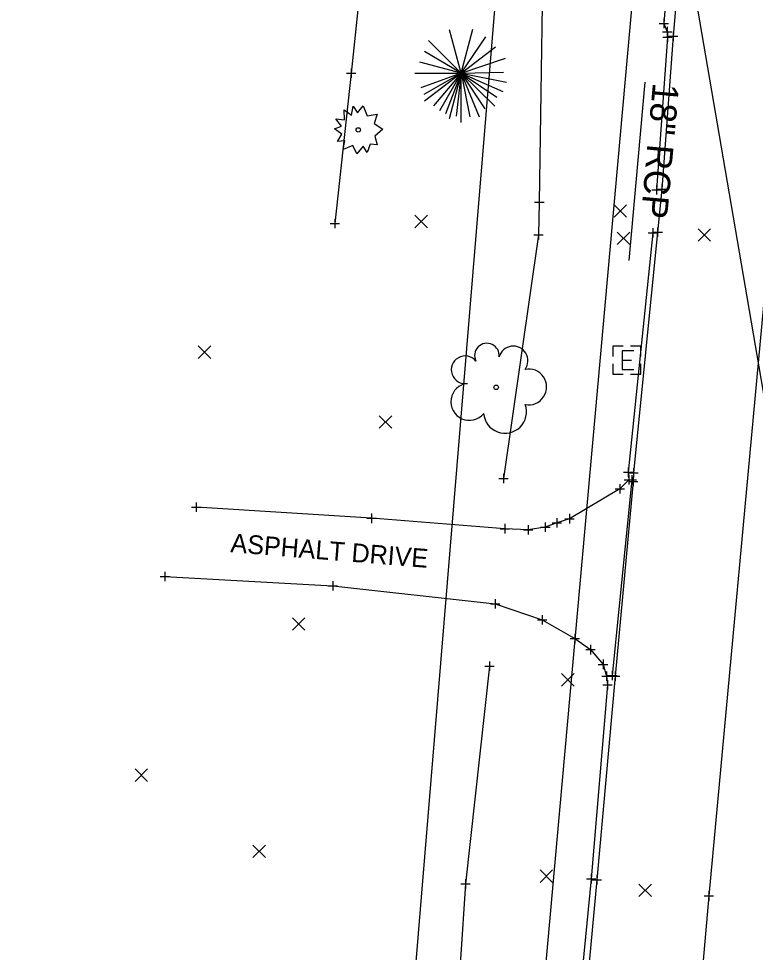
# Model space of a CAD drawing. Extents: x 1380550 to 1381945, y 468927 to 470496.
# Drawn here: x 1381450.4 to 1381528.9, y 469059.1 to 469158.5 of the extents above; entities that cross this region are included whole.
import ezdxf

# ---------------------------------------------------------------- set-up
doc = ezdxf.new("R2010")
doc.units = 0
for name, color, linetype in [('DR_X_Storm_Sewer', 7, 'Continuous'), ('DR_X_Text', 7, 'Continuous'), ('PV_X_COP', 7, 'Continuous'), ('PV_X_Curb', 7, 'Continuous'), ('PV_X_Driveway', 7, 'Continuous'), ('PV_X_EOP', 7, 'Continuous'), ('RD_X_Text', 7, 'Continuous'), ('RW_X_Esmt_General', 7, 'Continuous'), ('SV_X_Random_Point', 7, 'Continuous'), ('SV_X_Shot_Marker', 7, 'Continuous'), ('SV_X_Toe_of_Slope', 7, 'Continuous'), ('UT_X_Electric', 7, 'Continuous'), ('UT_X_Electric_Cells', 7, 'Continuous'), ('UT_X_Telecom', 7, 'Continuous'), ('VG_X_Cells', 7, 'Continuous')]:
    doc.layers.add(name, color=color, linetype=linetype)

msp = doc.modelspace()

# ---------------------------------------------------------------- linework, layer by layer
at = {"layer": 'DR_X_Storm_Sewer'}
msp.add_line((1381528.037, 469296.447), (1381500.707, 468992.415), dxfattribs=at)
at = {"layer": 'DR_X_Text'}
msp.add_line((1381515.48, 469132.742), (1381517.189, 469151.751), dxfattribs=at)
at = {"layer": 'PV_X_COP'}
msp.add_lwpolyline([(1381585.986, 469815.579), (1381581.288, 469760.779), (1381580.3, 469747.86), (1381578.724, 469729.445), (1381576.782, 469708.953), (1381575.288, 469689.792), (1381572.756, 469657.561), (1381569.364, 469615.703), (1381565.36, 469567.235), (1381561.161, 469537.516), (1381558.939, 469486.814), (1381555.385, 469442.034), (1381550.974, 469391.016), (1381547.282, 469345.901), (1381541.953, 469289.547), (1381537.187, 469231.269), (1381533.052, 469168.087), (1381530.317, 469133.741), (1381523.968, 469065.081), (1381520.119, 469021.37), (1381518.183, 469001.306)], dxfattribs=at)
at = {"layer": 'PV_X_Curb'}
for points in [[(1381519.539, 469157.132), (1381519.552, 469156.548), (1381518.398, 469140.282)], [(1381518.001, 469135.707), (1381515.357, 469110.199), (1381515.44, 469109.406)], [(1381513.052, 469088.479), (1381513.166, 469087.561), (1381511.423, 469066.882), (1381509.25, 469044.753), (1381508.961, 469043.741)]]:
    msp.add_lwpolyline(points, dxfattribs=at)
at = {"layer": 'PV_X_Driveway'}
for points in [[(1381487.828, 469171.671), (1381488.593, 469175.573), (1381489.804, 469177.06), (1381491.802, 469178.459), (1381493.744, 469178.705), (1381499.999, 469178.744), (1381505.248, 469177.971), (1381510.629, 469175.939), (1381513.747, 469175.079), (1381519.994, 469168.458), (1381519.164, 469158.007), (1381519.539, 469157.132)], [(1381487.828, 469171.671), (1381485.847, 469152.719), (1381484.107, 469136.687)], [(1381515.44, 469109.406), (1381514.47, 469108.44), (1381509.128, 469105.258), (1381507.755, 469104.815), (1381506.539, 469104.347), (1381504.719, 469104.064), (1381502.211, 469104.195), (1381488.025, 469105.298), (1381469.315, 469106.486)], [(1381515.44, 469109.406), (1381515.744, 469109.385), (1381513.68, 469088.547), (1381513.052, 469088.479)], [(1381465.962, 469099.103), (1381483.882, 469098.094), (1381501.198, 469096.181), (1381506.201, 469094.476), (1381509.674, 469092.506), (1381511.352, 469091.307), (1381512.688, 469089.742), (1381513.052, 469088.479)]]:
    msp.add_lwpolyline(points, dxfattribs=at)
at = {"layer": 'PV_X_EOP'}
msp.add_lwpolyline([(1381521.185, 469168.775), (1381520.163, 469156.66), (1381518.942, 469140.358), (1381518.512, 469135.769), (1381515.95, 469110.139), (1381515.909, 469109.22), (1381513.991, 469088.497), (1381512.042, 469066.797), (1381509.955, 469044.61), (1381509.763, 469043.721), (1381507.936, 469023.869), (1381507.813, 469022.448), (1381506.018, 469002.556)], dxfattribs=at)
at = {"layer": 'RW_X_Esmt_General'}
msp.add_lwpolyline([(1381490.401, 469029.464), (1381590.199, 470237.184), (1380558.689, 470277.035)], dxfattribs=at)
at = {"layer": 'SV_X_Random_Point'}
for p, q in [((1381513.872, 469137.363), (1381515.206, 469138.698)), ((1381513.872, 469138.698), (1381515.206, 469137.363)), ((1381492.645, 469136.244), (1381493.979, 469137.579)), ((1381492.645, 469137.579), (1381493.979, 469136.244)), ((1381522.821, 469134.808), (1381524.155, 469136.143)), ((1381522.821, 469136.143), (1381524.155, 469134.808)), ((1381514.203, 469134.449), (1381515.537, 469135.784)), ((1381514.203, 469135.784), (1381515.537, 469134.449)), ((1381469.53, 469122.328), (1381470.864, 469123.663)), ((1381469.53, 469123.663), (1381470.864, 469122.328)), ((1381488.825, 469114.889), (1381490.159, 469116.224)), ((1381488.825, 469116.224), (1381490.159, 469114.889)), ((1381479.569, 469093.38), (1381480.903, 469094.715)), ((1381479.569, 469094.715), (1381480.903, 469093.38)), ((1381508.277, 469087.419), (1381509.611, 469088.754)), ((1381508.277, 469088.754), (1381509.611, 469087.419)), ((1381462.799, 469077.27), (1381464.133, 469078.606)), ((1381462.799, 469078.606), (1381464.133, 469077.27)), ((1381475.372, 469069.164), (1381476.706, 469070.499)), ((1381475.372, 469070.499), (1381476.706, 469069.164)), ((1381505.984, 469066.516), (1381507.318, 469067.851)), ((1381505.984, 469067.851), (1381507.318, 469066.516)), ((1381516.522, 469065.008), (1381517.856, 469066.343)), ((1381516.522, 469066.343), (1381517.856, 469065.008))]:
    msp.add_line(p, q, dxfattribs=at)
at = {"layer": 'SV_X_Shot_Marker'}
for p, q in [((1381518.664, 469158.007), (1381519.664, 469158.007)), ((1381519.164, 469158.507), (1381519.164, 469157.507)), ((1381519.164, 469158.007), (1381519.164, 469158.007)), ((1381519.039, 469157.132), (1381520.039, 469157.132)), ((1381519.039, 469157.132), (1381520.039, 469157.132)), ((1381519.539, 469157.632), (1381519.539, 469156.632)), ((1381519.539, 469157.632), (1381519.539, 469156.632)), ((1381519.539, 469157.132), (1381519.539, 469157.132)), ((1381519.539, 469157.132), (1381519.539, 469157.132)), ((1381519.552, 469157.048), (1381519.552, 469156.048)), ((1381520.163, 469157.16), (1381520.163, 469156.16)), ((1381519.052, 469156.548), (1381520.052, 469156.548)), ((1381519.552, 469156.548), (1381519.552, 469156.548)), ((1381519.663, 469156.66), (1381520.663, 469156.66)), ((1381520.163, 469156.66), (1381520.163, 469156.66)), ((1381485.847, 469153.219), (1381485.847, 469152.219)), ((1381485.347, 469152.719), (1381486.347, 469152.719)), ((1381485.847, 469152.719), (1381485.847, 469152.719)), ((1381517.898, 469140.282), (1381518.898, 469140.282)), ((1381518.398, 469140.782), (1381518.398, 469139.782)), ((1381518.398, 469140.282), (1381518.398, 469140.282)), ((1381518.442, 469140.358), (1381519.442, 469140.358)), ((1381518.942, 469140.858), (1381518.942, 469139.858)), ((1381518.942, 469140.358), (1381518.942, 469140.358)), ((1381505.898, 469139.484), (1381505.898, 469138.484)), ((1381505.398, 469138.984), (1381506.398, 469138.984)), ((1381505.898, 469138.984), (1381505.898, 469138.984)), ((1381484.107, 469137.187), (1381484.107, 469136.187)), ((1381483.607, 469136.687), (1381484.607, 469136.687)), ((1381484.107, 469136.687), (1381484.107, 469136.687)), ((1381518.001, 469136.207), (1381518.001, 469135.207)), ((1381518.512, 469136.269), (1381518.512, 469135.269)), ((1381505.326, 469135.51), (1381506.326, 469135.51)), ((1381505.826, 469136.01), (1381505.826, 469135.01)), ((1381505.826, 469135.51), (1381505.826, 469135.51)), ((1381517.501, 469135.707), (1381518.501, 469135.707)), ((1381518.001, 469135.707), (1381518.001, 469135.707)), ((1381518.012, 469135.769), (1381519.012, 469135.769)), ((1381518.512, 469135.769), (1381518.512, 469135.769)), ((1381514.857, 469110.199), (1381515.857, 469110.199)), ((1381515.357, 469110.699), (1381515.357, 469109.699)), ((1381515.357, 469110.199), (1381515.357, 469110.199)), ((1381515.95, 469110.639), (1381515.95, 469109.639)), ((1381501.565, 469109.541), (1381502.565, 469109.541)), ((1381502.065, 469110.041), (1381502.065, 469109.041)), ((1381502.065, 469109.541), (1381502.065, 469109.541)), ((1381514.94, 469109.406), (1381515.94, 469109.406)), ((1381514.94, 469109.406), (1381515.94, 469109.406)), ((1381514.94, 469109.406), (1381515.94, 469109.406)), ((1381515.244, 469109.385), (1381516.244, 469109.385)), ((1381515.409, 469109.22), (1381516.409, 469109.22)), ((1381515.44, 469109.906), (1381515.44, 469108.906)), ((1381515.44, 469109.906), (1381515.44, 469108.906)), ((1381515.44, 469109.906), (1381515.44, 469108.906)), ((1381515.44, 469109.406), (1381515.44, 469109.406)), ((1381515.44, 469109.406), (1381515.44, 469109.406)), ((1381515.44, 469109.406), (1381515.44, 469109.406)), ((1381515.45, 469110.139), (1381516.45, 469110.139)), ((1381515.744, 469109.885), (1381515.744, 469108.885)), ((1381515.744, 469109.385), (1381515.744, 469109.385)), ((1381515.909, 469109.72), (1381515.909, 469108.72)), ((1381515.909, 469109.22), (1381515.909, 469109.22)), ((1381515.95, 469110.139), (1381515.95, 469110.139)), ((1381513.97, 469108.44), (1381514.97, 469108.44)), ((1381514.47, 469108.94), (1381514.47, 469107.94)), ((1381514.47, 469108.44), (1381514.47, 469108.44)), ((1381468.815, 469106.486), (1381469.815, 469106.486)), ((1381469.315, 469106.986), (1381469.315, 469105.986)), ((1381469.315, 469106.486), (1381469.315, 469106.486)), ((1381487.525, 469105.298), (1381488.525, 469105.298)), ((1381488.025, 469105.798), (1381488.025, 469104.798)), ((1381488.025, 469105.298), (1381488.025, 469105.298)), ((1381507.755, 469105.315), (1381507.755, 469104.315)), ((1381508.628, 469105.258), (1381509.628, 469105.258)), ((1381509.128, 469105.758), (1381509.128, 469104.758)), ((1381509.128, 469105.258), (1381509.128, 469105.258)), ((1381502.211, 469104.695), (1381502.211, 469103.695)), ((1381504.719, 469104.564), (1381504.719, 469103.564)), ((1381506.039, 469104.347), (1381507.039, 469104.347)), ((1381506.539, 469104.847), (1381506.539, 469103.847)), ((1381506.539, 469104.347), (1381506.539, 469104.347)), ((1381507.255, 469104.815), (1381508.255, 469104.815)), ((1381507.755, 469104.815), (1381507.755, 469104.815)), ((1381501.711, 469104.195), (1381502.711, 469104.195)), ((1381502.211, 469104.195), (1381502.211, 469104.195)), ((1381504.219, 469104.064), (1381505.219, 469104.064)), ((1381504.719, 469104.064), (1381504.719, 469104.064)), ((1381465.962, 469099.603), (1381465.962, 469098.603)), ((1381465.462, 469099.103), (1381466.462, 469099.103)), ((1381465.962, 469099.103), (1381465.962, 469099.103)), ((1381483.882, 469098.594), (1381483.882, 469097.594)), ((1381483.382, 469098.094), (1381484.382, 469098.094)), ((1381483.882, 469098.094), (1381483.882, 469098.094)), ((1381501.198, 469096.681), (1381501.198, 469095.681)), ((1381500.698, 469096.181), (1381501.698, 469096.181)), ((1381501.198, 469096.181), (1381501.198, 469096.181)), ((1381505.701, 469094.476), (1381506.701, 469094.476)), ((1381506.201, 469094.976), (1381506.201, 469093.976)), ((1381506.201, 469094.476), (1381506.201, 469094.476)), ((1381509.174, 469092.506), (1381510.174, 469092.506)), ((1381509.674, 469093.006), (1381509.674, 469092.006)), ((1381509.674, 469092.506), (1381509.674, 469092.506)), ((1381510.852, 469091.307), (1381511.852, 469091.307)), ((1381511.352, 469091.807), (1381511.352, 469090.807)), ((1381511.352, 469091.307), (1381511.352, 469091.307)), ((1381500.093, 469089.559), (1381501.093, 469089.559)), ((1381500.593, 469090.059), (1381500.593, 469089.059)), ((1381500.593, 469089.559), (1381500.593, 469089.559)), ((1381512.188, 469089.742), (1381513.188, 469089.742)), ((1381512.688, 469090.242), (1381512.688, 469089.242)), ((1381512.688, 469089.742), (1381512.688, 469089.742)), ((1381512.552, 469088.479), (1381513.552, 469088.479)), ((1381512.552, 469088.479), (1381513.552, 469088.479)), ((1381512.552, 469088.479), (1381513.552, 469088.479)), ((1381513.052, 469088.979), (1381513.052, 469087.979)), ((1381513.052, 469088.979), (1381513.052, 469087.979)), ((1381513.052, 469088.979), (1381513.052, 469087.979)), ((1381513.052, 469088.479), (1381513.052, 469088.479)), ((1381513.052, 469088.479), (1381513.052, 469088.479)), ((1381513.052, 469088.479), (1381513.052, 469088.479)), ((1381513.18, 469088.547), (1381514.18, 469088.547)), ((1381513.491, 469088.497), (1381514.491, 469088.497)), ((1381513.68, 469089.047), (1381513.68, 469088.047)), ((1381513.68, 469088.547), (1381513.68, 469088.547)), ((1381513.991, 469088.997), (1381513.991, 469087.997)), ((1381513.991, 469088.497), (1381513.991, 469088.497)), ((1381512.666, 469087.561), (1381513.666, 469087.561)), ((1381513.166, 469088.061), (1381513.166, 469087.061)), ((1381513.166, 469087.561), (1381513.166, 469087.561)), ((1381498.034, 469066.868), (1381498.034, 469065.868)), ((1381510.923, 469066.882), (1381511.923, 469066.882)), ((1381511.423, 469067.382), (1381511.423, 469066.382)), ((1381511.423, 469066.882), (1381511.423, 469066.882)), ((1381511.542, 469066.797), (1381512.542, 469066.797)), ((1381512.042, 469067.297), (1381512.042, 469066.297)), ((1381512.042, 469066.797), (1381512.042, 469066.797)), ((1381497.534, 469066.368), (1381498.534, 469066.368)), ((1381498.034, 469066.368), (1381498.034, 469066.368)), ((1381523.968, 469065.581), (1381523.968, 469064.581)), ((1381523.468, 469065.081), (1381524.468, 469065.081)), ((1381523.968, 469065.081), (1381523.968, 469065.081))]:
    msp.add_line(p, q, dxfattribs=at)
at = {"layer": 'SV_X_Toe_of_Slope'}
for points in [[(1381506.403, 469174.002), (1381505.898, 469138.984), (1381505.826, 469135.51), (1381502.065, 469109.541)], [(1381500.593, 469089.559), (1381498.034, 469066.368), (1381496.433, 469042.299)]]:
    msp.add_lwpolyline(points, dxfattribs=at)
at = {"layer": 'UT_X_Electric'}
msp.add_lwpolyline([(1381665.562, 470247.404), (1381595.795, 470220.833), (1381581.264, 470018.199), (1381571.968, 469887.64), (1381559.775, 469757.408), (1381543.86, 469565.781), (1381529.165, 469390.12), (1381515.279, 469203.101), (1381540.8, 469054.263)], dxfattribs=at)
at = {"layer": 'UT_X_Electric_Cells'}
for p, q in [((1381514.733, 469122.135), (1381515.733, 469122.135)), ((1381515.233, 469122.135), (1381515.233, 469122.135))]:
    msp.add_line(p, q, dxfattribs=at)
for points in [[(1381514.833, 469123.635), (1381513.733, 469123.635), (1381513.733, 469122.535)], [(1381515.983, 469123.135), (1381514.733, 469123.135), (1381514.733, 469121.135), (1381515.983, 469121.135)], [(1381516.733, 469122.535), (1381516.733, 469123.635), (1381515.633, 469123.635)], [(1381513.733, 469121.735), (1381513.733, 469120.635), (1381514.833, 469120.635)], [(1381515.633, 469120.635), (1381516.733, 469120.635), (1381516.733, 469121.735)]]:
    msp.add_lwpolyline(points, dxfattribs=at)
at = {"layer": 'UT_X_Telecom'}
msp.add_lwpolyline([(1381665.562, 470247.404), (1381595.346, 470217.51), (1381581.264, 470018.199), (1381571.968, 469887.64), (1381559.775, 469757.408), (1381543.86, 469565.781), (1381529.165, 469390.12), (1381515.279, 469203.101), (1381540.8, 469054.263)], dxfattribs=at)
at = {"layer": 'VG_X_Cells'}
for p, q in [((1381497.558, 469152.715), (1381496.323, 469157.329)), ((1381497.558, 469152.715), (1381498.815, 469157.414)), ((1381497.558, 469152.715), (1381494.068, 469156.202)), ((1381497.558, 469152.715), (1381500.213, 469156.6)), ((1381497.558, 469152.715), (1381493.651, 469155.012)), ((1381497.558, 469152.715), (1381501.215, 469155.52)), ((1381497.558, 469152.715), (1381502.295, 469154.322)), ((1381497.558, 469152.715), (1381493.145, 469153.899)), ((1381492.623, 469152.715), (1381497.558, 469152.715)), ((1381497.558, 469152.715), (1381493.268, 469151.154)), ((1381497.558, 469152.715), (1381493.575, 469150.434)), ((1381497.558, 469152.715), (1381493.651, 469149.72)), ((1381497.558, 469152.715), (1381494.613, 469149.249)), ((1381497.558, 469152.715), (1381495.24, 469148.7)), ((1381497.558, 469152.715), (1381495.893, 469148.375)), ((1381497.558, 469152.715), (1381496.295, 469147.859)), ((1381497.558, 469152.715), (1381497.016, 469148.124)), ((1381497.558, 469152.715), (1381502.068, 469152.807)), ((1381497.558, 469147.475), (1381497.558, 469152.715)), ((1381497.558, 469152.715), (1381498.48, 469148.079)), ((1381497.558, 469152.715), (1381499.491, 469148.047)), ((1381497.558, 469152.715), (1381500.095, 469148.922)), ((1381497.558, 469152.715), (1381501.146, 469149.194)), ((1381497.558, 469152.715), (1381501.38, 469150.16)), ((1381497.558, 469152.715), (1381502.023, 469150.774)), ((1381497.558, 469152.715), (1381502.386, 469151.757))]:
    msp.add_line(p, q, dxfattribs=at)
msp.add_lwpolyline([(1381486.51, 469148.486), (1381487.115, 469149.221), (1381487.53, 469148.168), (1381488.622, 469148.348), (1381488.283, 469147.336), (1381489.228, 469146.741), (1381488.372, 469146.006), (1381488.622, 469145.093), (1381487.868, 469145.161), (1381487.543, 469144.248), (1381487.115, 469144.939), (1381486.437, 469144.123), (1381486.008, 469145.009), (1381484.988, 469144.579), (1381485.18, 469145.521), (1381484.368, 469145.438), (1381484.842, 469146.228), (1381484.073, 469146.796), (1381484.812, 469147.059), (1381484.205, 469147.863), (1381485.137, 469147.753), (1381485.107, 469148.791), (1381485.86, 469148.223), (1381486.067, 469149.208), (1381486.51, 469148.486)], dxfattribs=at)
for centre, radius in [((1381486.594, 469146.676), 0.23), ((1381501.294, 469119.253), 0.24)]:
    msp.add_circle(centre, radius, dxfattribs=at)
for centre, radius, start, end in [((1381500.31, 469122.621), 1.317, 354.0047, 205.97412), ((1381503.12, 469122.083), 1.553, 323.82996, 165.0376), ((1381497.985, 469121.118), 1.471, 39.06254, 279.54124), ((1381504.754, 469119.289), 1.915, 259.14531, 101.45961), ((1381498.441, 469117.705), 1.974, 96.17219, 320.57371), ((1381502.24, 469116.648), 2.284, 184.94757, 19.45715)]:
    msp.add_arc(centre, radius, start, end, dxfattribs=at)

# ---------------------------------------------------------------- texts
at = {"layer": 'DR_X_Text'}
msp.add_text('18" RCP', height=2.8, rotation=264.86338, dxfattribs=at).set_placement((1381518.015, 469151.737))
at = {"layer": 'RD_X_Text'}
msp.add_text('ASPHALT DRIVE', height=2, rotation=355.44278, dxfattribs=at).set_placement((1381472.927, 469101.697))

doc.saveas('drawing.dxf')
